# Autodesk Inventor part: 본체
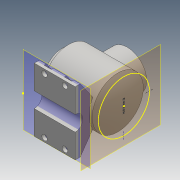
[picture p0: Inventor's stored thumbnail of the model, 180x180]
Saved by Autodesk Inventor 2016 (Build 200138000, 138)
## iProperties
Created: 2021-04
Part Number: 본체
Material: Generic
Document SubType Name: Modeling
Designer: user
Density: 1 g/cm^3
Appearance: Default
Author: user
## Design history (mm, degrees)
sketch "스케치3"
  geometry: L1 (0, 0)-(120, 0); L2 (0, 0)-(0, 38); L3 (0, 38)-(12, 38); L4 (12, 38)-(12, 50); L5 (12, 50)-(108.336, 50); L6 (120, 50)-(120, 0); L7 (108.336, 50)-(120, 50); A1 r 113 centre (7, 0) between (120, 0) and (108.336, 50)
  constraints: 15 end point, 5 perpendicular, 2 point on circle, 1 centre point, 1 horizontal, 1 horizontal alignment, 1 vertical
  dimensions: "d8" = 12 distance of L2.end L3.end; "d9" = 108 distance of L4.end L6.start; "d10" = 76 diameter of L3 L1; "d11" = 100 diameter of L5 L1; "d12" = 226 diameter of A1
revolve "회전1" sketch "스케치3" stored, may be unused: angle "d13" = 90 deg
sketch "스케치4"
  geometry: 1 further point
feature "쉘1" dims "d14" = 10
node "작업 평면1"
node "작업 평면2"
sketch "스케치5"
  geometry: L1 (-67, 62)-(-77, 62); L2 (-77, 62)-(-77, -62); L3 (-77, -62)-(-67, -62); L4 (-38.258, 20.952)-(-67, 62); L5 (-67, -62)-(-38.195, -20.863); L6 (-38.195, -20.863)-(-45.294, -5.787); L7 (-45.294, -5.787)-(-42.988, 13.585); L8 (-42.988, 13.585)-(-38.258, 20.952); C1 r 50 at (0, 0) reference; 2 further points
  constraints: 16 end point, 2 perpendicular, 1 horizontal, 1 horizontal alignment, 1 midpoint
  dimensions: "d20" = 10 distance of L1.start L1.end; "d21" = 10 distance of L2.end L3.end; "d22" = 124 distance of L1.end L2.end; "d23" = 77 distance from line of point (0, 0) L2
extrude "돌출2" join sketch "스케치5" stored distance "d24" = 80; taper "d25" = 0 deg
sketch "스케치6"
  geometry: L1 (-62, -77)-(62, -77) reference; C1 r 15 at (0, -77); 1 further point
  constraints: 1 centre point, 1 midpoint
  dimensions: "d26" = 30 diameter of C1
extrude "돌출3" cut sketch "스케치6" stored distance "d27" = 80; taper "d28" = 0 deg
node "작업 평면3"
node "작업 평면4"
sketch "스케치7"
  geometry: L1 (102, -24)-(102, -100) reference; C1 r 38 at (40, -62); 2 further points
  constraints: 1 centre point, 1 horizontal alignment, 1 midpoint
  dimensions: "d30" = 62 distance from line of L1 C1.centre; "d31" = 76 diameter of C1
extrude "돌출4" join sketch "스케치7" stored distance "d32" = 80; taper "d33" = 0 deg
sketch "스케치9"
  geometry: L1 (-22, -40)-(-101.916, -40) reference; L2 (-22, 40)-(-101.916, 40) reference; L3 (-10, -28)-(-22, -28) reference; L4 (-10, 28)-(-22, 28) reference; L5 (0, 38)-(0, -38) reference; L6 (0, 0)-(-10, 0); L7 (-10, 0)-(-10, -28); L8 (-10, -28)-(0, -28); L9 (0, -28)-(0, 0)
  constraints: 8 end point, 2 parallel, 1 horizontal, 1 perpendicular
revolve "회전2" sketch "스케치9" stored, may be unused: angle "d34" = 90 deg
hole "구멍1" diameter "d37" = 54; stored, may be unused: countersink angle "d41" = 90 deg, drill point angle "d43" = 118 deg; dims "d35" = 10, "d36" = 10, "d38" = 6, "d39" = 4, "d40" = 2, "d42" = 22
sketch "스케치10"
  geometry: C1 r 27 at (0, 0) reference; 2 further points
  dimensions: "d54" = 32.5 distance of C1.centre point (0, 32.5)
hole "구멍2" sketch "스케치10" at (0, 32.5) diameter "d44" = 3.242; stored, may be unused: countersink angle "d48" = 90 deg, drill point angle "d50" = 118 deg; dims "d45" = 8, "d46" = 4, "d47" = 2, "d49" = 10
sketch "스케치11"
  geometry: 1 further point
sketch "스케치12"
  geometry: 2 further points
  dimensions: "d58" = 32.5 distance of point (0, 0) point (0, 32.5)
hole "구멍3" sketch "스케치12" at (0, 32.5) diameter "d59" = 3.242; stored, may be unused: countersink angle "d63" = 90 deg, drill point angle "d65" = 118 deg; dims "d60" = 8, "d61" = 4, "d62" = 2, "d64" = 10
sketch "스케치13"
  geometry: L1 (-80, 0)-(0, 0) reference; L2 (-80, -47)-(0, -47) reference; L3 (0, 0)-(0, -47) reference; L4 (-80, 0)-(0, 0) reference; L5 (-80, -47)-(-80, 0) reference; L6 (-80, -77)-(-80, -47) reference; L7 (-80, -62)-(-49.604, -62); C1 r 5.302 at (-60, -8); 1 further point
  constraints: 2 end point, 1 centre point, 1 horizontal, 1 midpoint
  dimensions: "d69" = 8 distance from line of L1 C1.centre; "d70" = 20 distance from line of L5 C1.centre
extrude "돌출5" cut sketch "스케치13" distance "d71" = 6; taper "d72" = 0 deg
node "작업 평면5"
sketch "스케치16"
  geometry: 1 further point
sketch "스케치17" dims "d81" = 14
  geometry: L1 (67, 17.665)-(53, 17.665); L2 (53, 17.665)-(53, -8); L3 (53, -8)-(67, -8); L4 (67, -8)-(67, 17.665); C1 r 5.302 at (60, -8) reference; 3 further points
  constraints: 8 end point, 2 coincident, 2 parallel, 1 horizontal, 1 horizontal alignment, 1 midpoint, 1 perpendicular, 2 other
extrude "돌출7" cut sketch "스케치17" distance "d82" = 20; taper "d83" = 0 deg
node "작업 평면7"
sketch "스케치18"
  geometry: 1 further point
node "작업 평면8"
sketch "스케치19"
  geometry: A1 r 50 centre (0, 0) between (50, 0) and (0, -50) reference; 2 further points
  constraints: 2 point on circle, 1 coincident, 1 vertical alignment, 1 other
node "솔리드2"
pattern_circular "원형 패턴2" dims angle "d56" = 360 deg
pattern_circular "원형 패턴3" dims angle "d67" = 360 deg
pattern_linear "직사각형 패턴2"
mirror "대칭2"
node "투영된 루프1"
other parameters: "d15" = 62, "d18" = 55 deg, "d19" = 55 deg, "d29" = -142, "d74" = -6
